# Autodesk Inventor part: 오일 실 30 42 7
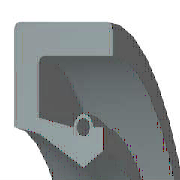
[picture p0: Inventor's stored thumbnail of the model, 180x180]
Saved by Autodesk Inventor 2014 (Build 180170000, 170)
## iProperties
IsCustomPart: 1
Created: 2012-02
Part Number: 오일 실 30 42 7
Material: 고무
Description: 오일 실 - 스프링 장착, 금속 케이스 SM
Document SubType Name: Modeling
Standard: JIS B 2402
Designer: mdu-01
Standards Organization: JIS
Language: ko-KR
Size Designation: 30 42 7 A
Categories: <MemberInstance><Categories><Category DisplayName="샤프트 부품" InternalName="7f7aeb1f-a693-4053-b835-cee3144e0d98" Mnemonic="SHFT"><Category DisplayName="실링" Intern
Density: 0.93 g/cm^3
Appearance: Rubber-Black
Author: mdu-01
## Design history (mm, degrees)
body "Solid1"
revolve "회전1" stored, may be unused: angle "d33" = 360 deg
fillet "모깎기1" dims "d34" = 0.35 (= 0.05 x b)
chamfer "모따기1" distance "d35" = 0.7 (= 0.1 x b); stored, may be unused: second distance "d36" = 0.35 (= 0.05 x b), angle "d41" = 45 deg
sketch "스케치2"
  geometry: L1 (16.457, -5.158)-(17.021, -7); L2 (15.857, -4.55)-(16.457, -5.158); L3 (15, -1.75)-(15.857, -4.55); L4 (15.8, -0.875)-(15, -1.75); L5 (17.141, -0.875)-(15.8, -0.875); L6 (17.141, -1.575)-(17.141, -0.875); L7 (17.141, -5.25)-(17.141, -2.975); L8 (18.6, -5.25)-(17.141, -5.25); L9 (19.8, -1.75)-(18.6, -5.25); L10 (19.8, 0)-(19.8, -1.75); L11 (21, 0)-(19.8, 0); L12 (21, -7)-(21, 0); L13 (17.021, -7)-(21, -7); L14 (0, -9.6)-(0, 1.6) reference; L15 (28, 0)-(14, 0) reference; A1 r 0.7 centre (17.141, -2.275) between (17.141, -2.975) and (17.141, -1.575)
  constraints: 26 end point, 4 horizontal, 4 vertical, 2 point on circle, 1 centre point, 1 collinear, 1 parallel
  dimensions: "d2" = 7 distance of L12.start L11.start (= b); "d4" = 0.875 vertical distance of L10.start L5.start (= 0.125 x b); "d6" = 1.2 distance of L11.start L10.start (= 0.1 x dd - 0.1 x Diam); "d8" = 1.75 distance of L10.start L9.start (= 0.25 x b); "d10" = 1.75 vertical distance of L8.start L1.end (= 0.25 x b); "d12" = 1.2 horizontal distance of L9.start L8.start (= 0.1 x dd - 0.1 x Diam); "d14" = 0.7 radius of A1 (= 0.1 x b); "d16" = 0 horizontal distance of A1.centre L7.end; "d18" = 0.7 distance of L6.start L5.start (= 0.1 x b); "d20" = 0.8 horizontal distance of L4.start L3.start (= 0.0666667 x dd - 0.0666667 x Diam); "d22" = 0.12 horizontal distance of L7.start L1.end (= 0.01 x dd - 0.01 x Diam); "d24" = 0.875 vertical distance of L4.start L3.start (= 0.125 x b); "d26" = 2.8 vertical distance of L3.start L2.start (= 0.4 x b); "d28" = 0.85714 horizontal distance of L3.start L2.start (= 0.0714286 x dd - 0.0714286 x Diam); "d30" = 1.84211 vertical distance of L1.start L1.end (= 0.263158 x b); "d32" = 0.6 horizontal distance of L2.start L1.start (= 0.05 x dd - 0.05 x Diam); "d37" = 0 distance between parallel lines of L15 L11; "d38" = 21 distance between parallel lines of L14 L12 (= 0.5 x dd); "d39" = 15 distance from line of L14 L3.start (= 0.5 x Diam)
other parameters: "dd" = 42 [user parameter; used in 7 equation terms], "b" = 7 [user parameter; used in 12 equation terms], "d1" = 8 (derived), "d3" = 1 (derived), "d5" = 2 (derived), "d7" = 2 (derived), "d9" = 2 (derived), "d11" = 2 (derived), "d13" = 0.8 (derived), "d15" = 0 (derived), "d17" = 0.8 (derived), "d19" = 1.33333 (derived), "d21" = 0.2 (derived), "d23" = 1 (derived), "d25" = 3.2 (derived), "d27" = 1.42857 (derived), "d29" = 2.10526 (derived), "d31" = 1 (derived), "d40" = 0
